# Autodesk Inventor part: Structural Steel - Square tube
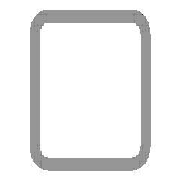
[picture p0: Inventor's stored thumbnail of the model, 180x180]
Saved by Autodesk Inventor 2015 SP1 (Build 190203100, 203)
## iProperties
_CCFamilyMember: 2
_CCFamilyDisplayName: ISO 4019 (Square) - Structural steels - Cold-formed, welded, structural hollow sections
_FrameMemberDoc: Frame Member File
_Version: 15.0.0
_GetPNFromCC: 1
Created: 2011-06
Part Number: Structural Steel - Square tube
Material: Stainless Steel
Document SubType Name: Modeling
Standard: ISO
Designer: Guilherme Augusto Franco de Souza
Standard Revision: Second edition 2001-09-01
Standards Organization: ISO
Language: en-US
Size Designation: 25x25x2
Categories: <MemberInstance><Categories><Category DisplayName="Structural Shapes" InternalName="089c4875-fa83-4c05-b084-43b9cc11f5ed" Mnemonic="GRDR"><CategoryParameter Dis
Stock Number: 25x25x2
Density: 8.08 g/cm^3
Description: ISO 4019 - 25x25x2
Appearance: Steel
G_L: 700,000 mm
G_W: 25,000 mm
G_H: 25,000 mm
+7BA6D68B-4ACB-437B-AEF3-661DB70B6601+CUTDETAIL1: Miter 45,00 deg
+F6DD3AC6-5505-4A6A-B595-A047C3CF548A+CUTDETAIL2: Miter 45,00 deg
IsCustomPart: 1
Author: Guilherme Augusto Franco de Souza
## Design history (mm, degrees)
node "Start plane"
node "End plane"
sketch "Sketch"
  geometry: L1 (-12.5, -8.5)-(-12.5, 8.5); L2 (-8.5, 12.5)-(8.5, 12.5); L3 (12.5, 8.5)-(12.5, -8.5); L4 (8.5, -12.5)-(-8.5, -12.5); L5 (-8.5, 10.5)-(8.5, 10.5); L6 (10.5, 8.5)-(10.5, -8.5); L7 (8.5, -10.5)-(-8.5, -10.5); L8 (-10.5, -8.5)-(-10.5, 8.5); L9 (0, 18.66)-(0, -18.66) reference; L10 (-18.66, 0)-(18.66, 0) reference; A1 r 4 centre (-8.5, -8.5) between (-12.5, -8.5) and (-8.5, -12.5); A2 r 4 centre (8.5, 8.5) between (12.5, 8.5) and (8.5, 12.5); A3 r 4 centre (-8.5, 8.5) between (-8.5, 12.5) and (-12.5, 8.5); A4 r 4 centre (8.5, -8.5) between (8.5, -12.5) and (12.5, -8.5); A5 r 2 centre (-8.5, 8.5) between (-8.5, 10.5) and (-10.5, 8.5); A6 r 2 centre (8.5, 8.5) between (10.5, 8.5) and (8.5, 10.5); A7 r 2 centre (8.5, -8.5) between (8.5, -10.5) and (10.5, -8.5); A8 r 2 centre (-8.5, -8.5) between (-10.5, -8.5) and (-8.5, -10.5)
  constraints: 16 end point, 16 point on circle, 8 centre point, 8 tangent, 4 parallel, 3 equal radius, 2 perpendicular, 7 other
  dimensions: "d7" = 4 radius of A1 (= G_IR); "d9" = 25 distance between parallel lines of L1 L3 (= G_W); "d11" = 25 distance between parallel lines of L2 L4 (= G_H); "d12" = 2 distance between parallel lines of L3 L6 (= G_T); "d15" = 12.5 distance between parallel lines of L9 L3 (= 0.5 x d9); "d16" = 12.5 distance between parallel lines of L2 L10 (= 0.5 x d11)
extrude "Body" new body sketch "Sketch" stored distance "d3" = 700 (= G_L); taper "d4" = 0 deg
node "Driven Length"
  sketch "Sketch3"
    geometry: L1 (0, 0)-(10, 0) reference
    constraints: 2 end point, 1 horizontal
  workplane "Work Plane3"
  sketch "Sketch4"
    geometry: L1 (-2, 0.141)-(12, 0.141) reference; L2 (-2, 699.859)-(12, 699.859) reference
    dimensions: "d18" = 699.71716 distance between parallel lines of L1 L2 (derived)
workplane "Work Plane4"
split "Split1"
workplane "Work Plane5"
split "Split2"
body "Solid1"
other parameters: "G_W" = 25 [user parameter; used in 1 equation term], "G_H" = 25 [user parameter; used in 1 equation term], "G_T" = 2 [user parameter; used in 1 equation term], "G_IR" = 4 [user parameter; used in 1 equation term], "G_L" = 700 [user parameter; used in 1 equation term], "G_OFFSET_START" = -0.14142 [user parameter; used in 1 equation term], "G_OFFSET_END" = -0.14142 [user parameter; used in 1 equation term], "d13" = 0.14142 (= -G_OFFSET_START), "d14" = 699.85858 (= G_OFFSET_END + B_L), "d17" = 90 deg, "MAS" = 0.136 [user parameter]
